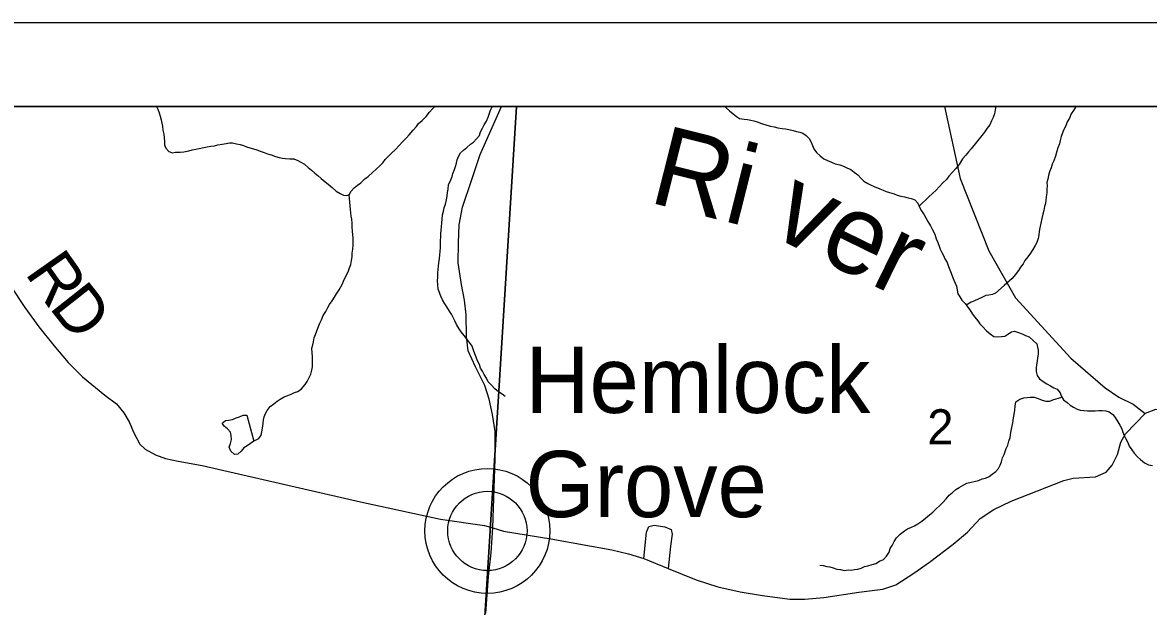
# Model space of a CAD drawing. Extents: x -20.2 to 34, y 0 to 22.
# Drawn here: x 6.507 to 7.849, y 20.305 to 21 of the extents above; entities that cross this region are included whole.
import ezdxf

# ---------------------------------------------------------------- set-up
doc = ezdxf.new("R2010")
doc.units = 0
for name, color, linetype in [('Default', 7, 'Continuous'), ('GM_X_County_Road', 7, 'Continuous'), ('GM_X_Minor_River', 7, 'Continuous'), ('GM_X_Minor_River_Text', 7, 'Continuous'), ('GM_X_Section_Text', 7, 'Continuous'), ('GM_X_Township_Road', 7, 'Continuous'), ('GM_X_Township_Road_Text', 7, 'Continuous'), ('GM_X_Unincorporated', 7, 'Continuous'), ('GM_X_Unincorporated_Location', 7, 'Continuous'), ('GM_X_Unincorporated_Text', 7, 'Continuous'), ('SH_Cut_Line', 7, 'Continuous'), ('SH_Data', 7, 'Continuous')]:
    doc.layers.add(name, color=color, linetype=linetype)

msp = doc.modelspace()

# ---------------------------------------------------------------- linework, layer by layer
at = {"layer": 'Default'}
for points in [[(8.1508, 20.9), (2.1, 20.9), (2.1, 19.2514), (2.9253, 19.1951), (4.084, 19.1299), (4.129, 19.1285), (4.5, 19.1063), (4.5753, 19.1032), (5.0716, 19.0751), (5.6168, 19.0426), (5.628, 19.0419), (5.9006, 19.026), (6.5332, 18.9927), (7.3871, 18.9465), (7.5395, 18.9382), (7.8072, 18.9199), (8.043, 18.9097), (8.0485, 19.0914), (8.0709, 19.4522), (8.1316, 20.5548)], [(7.0959, 20.9), (6.0195, 20.9), (6.0189, 20.878), (6.0052, 20.4384), (5.9839, 20.0577), (7.0409, 20.0115)], [(8.1484, 20.9), (7.0959, 20.9), (7.0409, 20.0115), (8.0972, 19.9556)]]:
    msp.add_lwpolyline(points, close=True, dxfattribs=at)
at = {"layer": 'GM_X_County_Road'}
msp.add_lwpolyline([(7.0595, 20.2967), (7.0625, 20.3401), (7.0659, 20.3686), (7.0679, 20.398), (7.0704, 20.4803), (7.0704, 20.5131), (7.0673, 20.533), (7.0634, 20.5515), (7.0583, 20.5677), (7.0471, 20.5901), (7.0385, 20.6089), (7.0365, 20.626), (7.0359, 20.652), (7.034, 20.6694), (7.0303, 20.6878), (7.0264, 20.7139), (7.0267, 20.7377), (7.0278, 20.7592), (7.0317, 20.7802), (7.0424, 20.8119), (7.0527, 20.8429), (7.0782, 20.9)], dxfattribs=at)
at = {"layer": 'GM_X_Minor_River'}
for points in [[(6.667, 20.9), (6.6685, 20.8968), (6.6701, 20.8923), (6.6713, 20.8885), (6.6728, 20.8843), (6.6736, 20.8801), (6.6744, 20.8764), (6.6748, 20.8718), (6.6757, 20.8669), (6.6761, 20.8627), (6.6765, 20.8582), (6.6765, 20.8544), (6.6781, 20.8502), (6.6816, 20.8464), (6.6861, 20.845), (6.6899, 20.8454), (6.6952, 20.8455), (6.6998, 20.8459), (6.7055, 20.8471), (6.7096, 20.8483), (6.7138, 20.8491), (6.718, 20.8499), (6.7233, 20.8511), (6.7274, 20.8519), (6.732, 20.8527), (6.7361, 20.8531), (6.7403, 20.8543), (6.7452, 20.8551), (6.7501, 20.8559), (6.7539, 20.8567), (6.7577, 20.8568), (6.7623, 20.8557), (6.7668, 20.8546), (6.7707, 20.8535), (6.7745, 20.852), (6.7783, 20.8509), (6.7828, 20.8495), (6.7866, 20.8484), (6.7916, 20.8465), (6.7954, 20.8451), (6.7992, 20.8436), (6.8038, 20.8425), (6.8087, 20.8403), (6.8133, 20.8392), (6.8171, 20.8385), (6.8209, 20.8381), (6.8258, 20.8378), (6.8308, 20.8375), (6.8353, 20.8356)], [(6.8353, 20.8356), (6.8392, 20.8338), (6.8434, 20.8312), (6.8476, 20.8274), (6.8518, 20.8241), (6.8556, 20.8207), (6.8594, 20.8177), (6.8633, 20.8143), (6.8679, 20.8102), (6.8717, 20.8076), (6.8763, 20.8034), (6.8813, 20.7993), (6.8858, 20.7963), (6.8897, 20.7945), (6.8935, 20.7938), (6.8972, 20.795), (6.8987, 20.7988), (6.9025, 20.803), (6.9066, 20.8061), (6.9104, 20.8092), (6.9153, 20.8138), (6.9194, 20.8168), (6.9243, 20.8215), (6.9288, 20.8253), (6.9333, 20.8292), (6.9367, 20.833), (6.9397, 20.8368), (6.9434, 20.8407), (6.9472, 20.8445), (6.9517, 20.8487), (6.9562, 20.8537), (6.9599, 20.8575), (6.9648, 20.8625), (6.9682, 20.8664), (6.9727, 20.8717), (6.9768, 20.876), (6.9794, 20.8798), (6.9836, 20.8833), (6.9885, 20.8879), (6.9922, 20.8932), (6.996, 20.8971), (6.9986, 20.9)], [(7.0028, 20.6823), (7.0023, 20.6879), (7.0019, 20.6921), (7.0022, 20.697), (7.0022, 20.702), (7.0025, 20.7058), (7.0029, 20.71), (7.0036, 20.7138), (7.0043, 20.7191), (7.0046, 20.7233), (7.005, 20.7274), (7.0053, 20.732), (7.0056, 20.7358), (7.0056, 20.7404), (7.0059, 20.7445), (7.0059, 20.7483), (7.0062, 20.7525), (7.0065, 20.7567), (7.0069, 20.7616), (7.0076, 20.7658), (7.0079, 20.7711), (7.009, 20.7753), (7.0097, 20.7791), (7.0112, 20.7837), (7.0127, 20.7887), (7.0134, 20.7932), (7.0137, 20.7974), (7.0144, 20.8016), (7.0151, 20.8069), (7.017, 20.8107), (7.0192, 20.8165), (7.0203, 20.8203), (7.0221, 20.8248), (7.0232, 20.8286), (7.0243, 20.8325), (7.0254, 20.8366), (7.0269, 20.8405), (7.0291, 20.8447), (7.0329, 20.8481), (7.0367, 20.8512), (7.0412, 20.855), (7.0449, 20.8577), (7.0483, 20.8616), (7.0517, 20.8654), (7.0532, 20.87), (7.0554, 20.8742), (7.0576, 20.878), (7.0602, 20.8826), (7.0621, 20.8872), (7.0636, 20.891), (7.065, 20.8956), (7.0669, 20.8994), (7.0672, 20.9)], [(7.3442, 20.9), (7.3458, 20.8983), (7.3496, 20.895)], [(7.6671, 20.9), (7.6664, 20.8959), (7.6653, 20.8913), (7.6639, 20.8867), (7.662, 20.8829), (7.6598, 20.8783), (7.6568, 20.8741), (7.6534, 20.8695), (7.6504, 20.8653), (7.6471, 20.8615), (7.6441, 20.8577), (7.6407, 20.8534), (7.6377, 20.8496), (7.6343, 20.8458), (7.6313, 20.842), (7.6272, 20.8377), (7.6235, 20.8309), (7.6193, 20.8263), (7.6156, 20.822), (7.6111, 20.817), (7.6081, 20.8132), (7.604, 20.809), (7.5995, 20.8044), (7.5961, 20.8005), (7.5916, 20.7963), (7.5871, 20.7925), (7.5756, 20.7814)], [(7.7627, 20.9), (7.762, 20.8992), (7.7594, 20.8954), (7.7568, 20.8912), (7.7549, 20.8862), (7.7519, 20.8817), (7.7505, 20.8771), (7.7479, 20.8725), (7.7464, 20.8687), (7.7449, 20.8641), (7.7438, 20.8595), (7.7427, 20.8554)], [(7.3496, 20.895), (7.3542, 20.8912), (7.358, 20.8879), (7.3618, 20.8856), (7.3672, 20.8849), (7.3713, 20.8846), (7.3751, 20.8839), (7.3789, 20.8828), (7.3828, 20.8817), (7.3877, 20.8798), (7.3942, 20.8776), (7.3987, 20.8765), (7.4029, 20.8758), (7.4071, 20.8747), (7.4124, 20.8737), (7.4166, 20.8733), (7.4204, 20.8726), (7.4254, 20.8715), (7.4295, 20.8704), (7.4334, 20.8693), (7.4372, 20.8682), (7.441, 20.8656), (7.4448, 20.8619), (7.4471, 20.8577), (7.4487, 20.8536), (7.4503, 20.8494), (7.4533, 20.8453), (7.4576, 20.8411), (7.4621, 20.8378), (7.4663, 20.8355), (7.4713, 20.8337), (7.4755, 20.8318), (7.4812, 20.8304), (7.4854, 20.8289), (7.4896, 20.8271), (7.4942, 20.8248), (7.4984, 20.8218), (7.5026, 20.8185), (7.506, 20.8147), (7.5099, 20.811), (7.5144, 20.8084), (7.5183, 20.8061), (7.5221, 20.8047), (7.5289, 20.8021), (7.5327, 20.8002), (7.5365, 20.7987), (7.5403, 20.7976), (7.5457, 20.7958), (7.5495, 20.7943), (7.5537, 20.7932), (7.5582, 20.7925), (7.5624, 20.7914), (7.5662, 20.7903), (7.5704, 20.7889), (7.5739, 20.7847), (7.5762, 20.7802), (7.5785, 20.7757), (7.5816, 20.7711), (7.5835, 20.7674), (7.5859, 20.7632), (7.589, 20.7579), (7.5913, 20.7538), (7.5944, 20.7478), (7.5959, 20.7425), (7.5979, 20.7379), (7.5995, 20.7338), (7.6006, 20.73), (7.6026, 20.7262), (7.6045, 20.7224), (7.6064, 20.7187), (7.6091, 20.7141), (7.6107, 20.7096), (7.6123, 20.7054), (7.6138, 20.7013), (7.6154, 20.6971), (7.617, 20.6933), (7.6201, 20.6862)], [(7.7427, 20.8554), (7.7409, 20.8508), (7.7398, 20.8466), (7.738, 20.8409), (7.7361, 20.8352), (7.7343, 20.8313), (7.7328, 20.8271), (7.7309, 20.8222), (7.7298, 20.818), (7.7288, 20.8134), (7.7277, 20.8096), (7.7281, 20.8055), (7.7277, 20.8017), (7.7278, 20.7971), (7.7271, 20.7922), (7.7267, 20.7884), (7.726, 20.7845), (7.7249, 20.7807), (7.7242, 20.7762), (7.7231, 20.7716), (7.7217, 20.7667), (7.7206, 20.7609), (7.7195, 20.7556), (7.7188, 20.7511), (7.7181, 20.7472), (7.7174, 20.7427), (7.7159, 20.7381), (7.7137, 20.7343), (7.711, 20.7297), (7.7084, 20.7255), (7.7051, 20.7209), (7.7017, 20.7167), (7.6995, 20.7125), (7.6965, 20.7087), (7.6939, 20.7048), (7.6901, 20.6995), (7.6864, 20.6953), (7.677, 20.6866)], [(6.8848, 20.6816), (6.8881, 20.6878), (6.89, 20.692), (6.8918, 20.6962), (6.8937, 20.7), (6.8959, 20.7042), (6.897, 20.708), (6.8985, 20.7118), (6.8996, 20.7164), (6.9003, 20.7209), (6.9003, 20.7255), (6.901, 20.7301), (6.9013, 20.735), (6.9012, 20.7388), (6.9012, 20.7434), (6.9008, 20.7472), (6.9007, 20.7517), (6.9003, 20.7563), (6.9003, 20.7612), (6.8998, 20.7657), (6.899, 20.7695), (6.8986, 20.7733), (6.8982, 20.7775), (6.8965, 20.7947)], [(7.6201, 20.6862), (7.6216, 20.6769), (7.6243, 20.6731), (7.6266, 20.6694), (7.6304, 20.6652), (7.6332, 20.6615), (7.6359, 20.6577), (7.6393, 20.6528), (7.642, 20.649), (7.6455, 20.6449), (7.6478, 20.6411), (7.6517, 20.6374), (7.6559, 20.6329), (7.6601, 20.6291), (7.6647, 20.6261), (7.6693, 20.6258), (7.6738, 20.6259), (7.6776, 20.6263), (7.6814, 20.629), (7.6855, 20.6317), (7.6893, 20.6325), (7.6939, 20.6307), (7.6984, 20.6292), (7.7023, 20.6274), (7.7068, 20.6255), (7.7114, 20.6214), (7.7157, 20.6173), (7.7168, 20.6135), (7.7173, 20.6097), (7.7173, 20.6051), (7.7166, 20.6006), (7.7163, 20.5968), (7.7156, 20.5922), (7.7152, 20.5884), (7.7149, 20.5842), (7.7161, 20.5797), (7.7192, 20.5755), (7.7234, 20.5725), (7.7276, 20.5696), (7.7322, 20.5673), (7.736, 20.5651), (7.7402, 20.5633), (7.7437, 20.5591), (7.7449, 20.5553), (7.7476, 20.5508), (7.7518, 20.5474), (7.7556, 20.5441), (7.7595, 20.5418), (7.7637, 20.5396), (7.7675, 20.5385), (7.772, 20.5378), (7.7762, 20.5375), (7.7804, 20.5375), (7.7853, 20.5376), (7.7899, 20.538), (7.7937, 20.5381), (7.7982, 20.5374), (7.802, 20.5363), (7.8062, 20.5333), (7.8093, 20.5295), (7.8124, 20.5246), (7.8147, 20.5205), (7.8171, 20.516), (7.8183, 20.5122), (7.8198, 20.508), (7.8218, 20.5042), (7.8241, 20.4997), (7.826, 20.4955), (7.8291, 20.491), (7.8318, 20.4873), (7.8357, 20.4828), (7.8395, 20.4794), (7.8441, 20.4756), (7.8487, 20.4734), (7.8537, 20.4723)], [(7.677, 20.6866), (7.6667, 20.6778), (7.663, 20.6759), (7.6588, 20.6751), (7.655, 20.6747), (7.6505, 20.6727), (7.6459, 20.6707), (7.6414, 20.6684), (7.6376, 20.6668), (7.6318, 20.6633)], [(6.7827, 20.5013), (6.7889, 20.5046), (6.7919, 20.5084), (6.7926, 20.5126), (6.7936, 20.5191), (6.794, 20.5229), (6.7947, 20.5267), (6.7954, 20.5305), (6.7969, 20.5343), (6.7991, 20.5381), (6.8025, 20.5427), (6.807, 20.5458), (6.8108, 20.5489), (6.8145, 20.5516), (6.819, 20.554), (6.8236, 20.5559), (6.8277, 20.5575), (6.8315, 20.5594), (6.8353, 20.5606), (6.8398, 20.5637), (6.8443, 20.5687), (6.8465, 20.5726), (6.8491, 20.5771), (6.851, 20.5813), (6.8521, 20.5859), (6.8528, 20.5901), (6.8531, 20.5943), (6.8531, 20.5985), (6.853, 20.6027), (6.8526, 20.6064), (6.8521, 20.6121), (6.8532, 20.616), (6.854, 20.6198), (6.855, 20.6243), (6.8565, 20.6285), (6.858, 20.633), (6.8602, 20.6381), (6.8617, 20.6419), (6.8635, 20.6461), (6.8657, 20.6511), (6.8687, 20.656), (6.8713, 20.6606), (6.8732, 20.6641), (6.8762, 20.6687), (6.8791, 20.6729), (6.8817, 20.6767), (6.8848, 20.6816)], [(7.0825, 20.5546), (7.0787, 20.5572), (7.0744, 20.5602), (7.0702, 20.5636), (7.066, 20.5681), (7.0622, 20.5722), (7.0602, 20.5764), (7.0575, 20.5809), (7.0556, 20.5847), (7.0532, 20.5884), (7.052, 20.5926), (7.0497, 20.5971), (7.0481, 20.6013), (7.0462, 20.6055), (7.0446, 20.6096), (7.0431, 20.6145), (7.04, 20.6191), (7.0365, 20.6236), (7.0338, 20.6273), (7.0299, 20.6315), (7.0276, 20.6352), (7.0245, 20.6405), (7.0226, 20.6447), (7.0206, 20.6485), (7.0187, 20.6526), (7.016, 20.6564), (7.0129, 20.6613), (7.0106, 20.665), (7.0079, 20.6696), (7.0059, 20.6741), (7.0028, 20.6823)], [(7.4572, 20.3537), (7.4614, 20.3534), (7.4656, 20.3523), (7.4694, 20.3516), (7.4732, 20.3505), (7.4774, 20.3491), (7.482, 20.3487), (7.4865, 20.3473), (7.4911, 20.3481), (7.4949, 20.3478), (7.4987, 20.3486), (7.5025, 20.349), (7.5066, 20.3502), (7.5104, 20.3521), (7.5146, 20.3529), (7.5195, 20.3545), (7.524, 20.3557), (7.5285, 20.3584), (7.5331, 20.3604), (7.5368, 20.3646), (7.5398, 20.3692), (7.5413, 20.3734), (7.5435, 20.3772), (7.5457, 20.3818), (7.5487, 20.3864), (7.5532, 20.3907), (7.5581, 20.3945), (7.5619, 20.3969), (7.5664, 20.3988), (7.5702, 20.4004), (7.574, 20.4031), (7.5788, 20.4062), (7.5834, 20.4097), (7.5879, 20.4135), (7.592, 20.417), (7.5958, 20.4208), (7.6003, 20.4247), (7.604, 20.4285), (7.6078, 20.4328), (7.6115, 20.437), (7.6153, 20.4401), (7.6194, 20.4439), (7.6235, 20.4463), (7.6288, 20.4494), (7.6326, 20.4513), (7.6375, 20.4525), (7.6413, 20.4533), (7.6462, 20.4545), (7.6508, 20.4565), (7.6545, 20.4573), (7.6591, 20.4593), (7.6628, 20.462), (7.667, 20.4651), (7.67, 20.4689), (7.6722, 20.4727), (7.6737, 20.4769), (7.6751, 20.4815), (7.677, 20.4857), (7.6792, 20.4926), (7.6814, 20.4968), (7.6825, 20.5013), (7.684, 20.5059), (7.6847, 20.5116), (7.6861, 20.5177), (7.6872, 20.5231), (7.6882, 20.5292), (7.689, 20.533), (7.6896, 20.5383), (7.69, 20.5432), (7.691, 20.5482), (7.6956, 20.5513), (7.7005, 20.5529), (7.7043, 20.5533), (7.7081, 20.5537), (7.7126, 20.5538), (7.7176, 20.5523), (7.7222, 20.5501), (7.7267, 20.549), (7.7313, 20.5491), (7.7351, 20.5506), (7.7458, 20.5538)], [(6.7829, 20.5015), (6.7753, 20.496), (6.7712, 20.4933), (6.7678, 20.4895), (6.7641, 20.486), (6.7599, 20.4856), (6.7557, 20.4893), (6.7537, 20.4942), (6.7552, 20.4988), (6.7563, 20.5034), (6.7562, 20.5083), (6.7554, 20.5121), (6.7516, 20.5159), (6.7477, 20.5192), (6.7454, 20.523), (6.7492, 20.5261), (6.7529, 20.5265), (6.7575, 20.5274), (6.762, 20.5293), (6.7658, 20.5305), (6.7703, 20.5325), (6.7749, 20.5325), (6.7829, 20.5015)]]:
    msp.add_lwpolyline(points, dxfattribs=at)
at = {"layer": 'GM_X_Township_Road'}
for points in [[(7.6058, 20.9), (7.6247, 20.8141), (7.6585, 20.7279), (7.6903, 20.6721), (7.7563, 20.6004), (7.7973, 20.5649), (7.8135, 20.5539), (7.8308, 20.5455), (7.845, 20.5342)], [(6.493, 20.6863), (6.5104, 20.6606), (6.5271, 20.6374), (6.5448, 20.6152), (6.5618, 20.5952), (6.5789, 20.5782), (6.6057, 20.5562), (6.6193, 20.5458), (6.628, 20.5351), (6.6344, 20.5244), (6.6401, 20.5114), (6.6474, 20.4978), (6.6537, 20.492), (6.6659, 20.4851), (6.6777, 20.4808), (6.6928, 20.4776), (6.7214, 20.4724), (6.9102, 20.4291), (7.0054, 20.4084), (7.0578, 20.4008), (7.0679, 20.398), (7.0805, 20.3944), (7.1367, 20.3851), (7.2095, 20.372), (7.2294, 20.3672), (7.2476, 20.3616), (7.2765, 20.3496), (7.3102, 20.3362), (7.3359, 20.3278), (7.3625, 20.3221), (7.3891, 20.3174), (7.4215, 20.3131), (7.4394, 20.3131), (7.462, 20.3151), (7.5039, 20.3215), (7.5325, 20.325), (7.5478, 20.3304), (7.5695, 20.3443), (7.588, 20.3572), (7.6161, 20.3787), (7.6331, 20.3932), (7.6484, 20.4091), (7.6646, 20.4201), (7.6851, 20.4299), (7.7479, 20.4545), (7.7591, 20.4574), (7.7857, 20.4588), (7.7985, 20.4646), (7.8054, 20.473), (7.8118, 20.4857), (7.8158, 20.5001), (7.8216, 20.51), (7.845, 20.5342)], [(8.186, 20.6111), (8.1757, 20.6012), (8.1363, 20.5578), (8.1318, 20.5543), (8.0848, 20.5165), (8.0544, 20.4943), (8.0415, 20.4829), (8.0301, 20.4774), (8.0161, 20.4748), (7.9933, 20.4754), (7.9721, 20.478), (7.9574, 20.485), (7.9245, 20.507), (7.8881, 20.5282), (7.8719, 20.5381), (7.8571, 20.5393), (7.845, 20.5342)], [(7.2476, 20.3616), (7.2507, 20.393), (7.2538, 20.3997), (7.2599, 20.4014), (7.2728, 20.3994), (7.2804, 20.3961), (7.2815, 20.3905), (7.2793, 20.3762), (7.2765, 20.3496)]]:
    msp.add_lwpolyline(points, dxfattribs=at)
at = {"layer": 'GM_X_Unincorporated'}
for radius in [0.0744, 0.0472]:
    msp.add_circle((7.0613, 20.3945), radius, dxfattribs=at)
at = {"layer": 'GM_X_Unincorporated_Location'}
msp.add_line((7.0613, 20.3945), (7.0613, 20.3945), dxfattribs=at)
at = {"layer": 'SH_Cut_Line'}
msp.add_lwpolyline([(5.7735, 14.1), (8.9, 14.1), (8.9, 20.9), (2.1, 20.9), (2.1, 14.1), (5.3953, 14.1), (5.7268, 14.1076)], close=True, dxfattribs=at)
at = {"layer": 'SH_Data'}
for p, q in [((2, 21), (9, 21)), ((2.1, 20.9), (8.9, 20.9))]:
    msp.add_line(p, q, dxfattribs=at)

# ---------------------------------------------------------------- texts
at = {"layer": 'GM_X_Minor_River_Text'}
for s, rotation, p in [('Ri', 345.9068, (7.2516, 20.7864)), ('ver', 333.9056, (7.3951, 20.7483))]:
    msp.add_text(s, height=0.0947, rotation=rotation, dxfattribs=at).set_placement(p)
at = {"layer": 'GM_X_Section_Text'}
msp.add_text('2', height=0.0419, rotation=0, dxfattribs=at).set_placement((7.5854, 20.4975))
at = {"layer": 'GM_X_Township_Road_Text'}
for s, rotation, p in [('R', 305.0758, (6.5095, 20.7016)), ('D', 308.2535, (6.5383, 20.6607))]:
    msp.add_text(s, height=0.0568, rotation=rotation, dxfattribs=at).set_placement(p)
at = {"layer": 'GM_X_Unincorporated_Text'}
for s, p in [('Hemlock', (7.1067, 20.535)), ('Grove', (7.1067, 20.4109))]:
    msp.add_text(s, height=0.07898, rotation=0, dxfattribs=at).set_placement(p)

doc.saveas('drawing.dxf')
